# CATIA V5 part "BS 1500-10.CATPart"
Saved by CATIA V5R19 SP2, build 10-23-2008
Part number: BS 1500-10
Bounding box of the stored display mesh (mm): x -31.459 to 31.459, y -31.459 to 31.459, z 0 to 64
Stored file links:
  C:\Users\Bora\Desktop\3D Katı model\BS serisi\BS 1500\BS 1500-10.CATPart
  C:\Program Files\Dassault Systemes\B19\intel_a\reffiles\standard\MetricThickPitch.txt
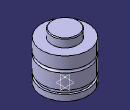
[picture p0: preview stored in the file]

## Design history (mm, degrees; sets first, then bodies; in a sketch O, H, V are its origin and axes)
Body1 (main body)
  Sketch1 on yz-plane, origin (0, 0, 0), H (0, 1, 0), V (0, 0, 1)
    point P1 (31.5, 37)
    point P2 (31.5, 33)
    point P3 (31.5, 37)
    point P7 (18, 63)
    point P9 (18, 63)
    point P14 (31.5, 33)
    arc A1 centre (31.5, 35) radius 2 from (31.5, 37) to (31.5, 33) ccw
    line L1 (31.5, 37) -> (31.5, 53)
    line L2 (31.5, 0) -> (31.5, 8)
    arc A2 centre (17, 63) radius 1 from (18, 63) to (17, 64) ccw
    line L3 (18, 63) -> (18, 53)
    line L4 (29, 13) -> (29, 8)
    line L5 (31.5, 13) -> (31.5, 33)
    line L6 (17, 64) -> (0, 64)
    point P15 (0, 64)
    line L7 (18, 53) -> (31.5, 53)
    line L8 (0, 0) -> (31.5, 0)
    line L9 (29, 13) -> (31.5, 13)
    line L10 (29, 8) -> (31.5, 8)
    tangency: L6 A2
    coincidence: P15 V, P1 P3, P2 P14, P7 P9
    horizontal: L7 H, L8 H, L9 H, L10 H
  Shaft1: profile Sketch1, axis Sketch1.V, angle 360
  Sketch2 on face of Shaft1 from Sketch1.L8, origin (0, 0, 0), H (1, 0, 0), V (0, -1, 0)
    point P1 (10, 0)
    distance P1 V = 10
  Hole1: placed by Sketch2, at (10, 0, 0) direction (0, 0, 1), diameter 6.647, depth 5, threaded "M8", thread diameter 8, thread depth 5, pitch 1.25
  CircPattern1: of Hole1, instances 2, angular step 180, axis from xy-plane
